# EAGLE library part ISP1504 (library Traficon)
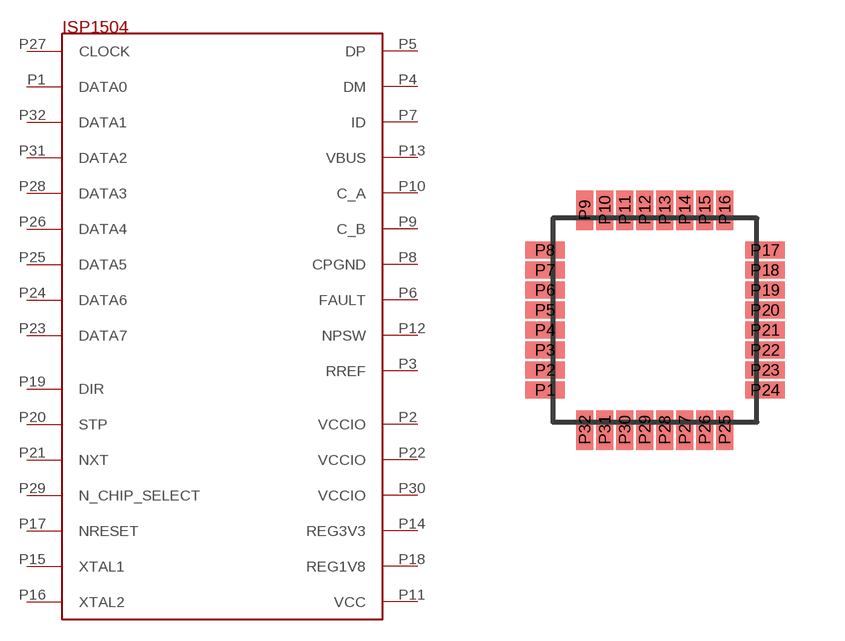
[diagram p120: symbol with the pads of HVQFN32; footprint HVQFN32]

Designator prefix U

## ISP1504  [HVQFN32]
P1  DATA0
P2  VCCIO
P3  RREF
P4  DM
P5  DP
P6  FAULT
P7  ID
P8  CPGND
P9  C_B
P10  C_A
P11  VCC
P12  NPSW
P13  VBUS
P14  REG3V3
P15  XTAL1
P16  XTAL2
P17  NRESET
P18  REG1V8
P19  DIR
P20  STP
P21  NXT
P22  VCCIO
P23  DATA7
P24  DATA6
P25  DATA5
P26  DATA4
P27  CLOCK
P28  DATA3
P29  N_CHIP_SELECT
P30  VCCIO
P31  DATA2
P32  DATA1

## Footprint HVQFN32 (pad centres in mm)
smd 0.99 x 0.42: P1 -2.75,-1.75; P2 -2.75,-1.25; P3 -2.75,-0.75; P4 -2.75,-0.25; P5 -2.75,0.25; P6 -2.75,0.75; P7 -2.75,1.25; P8 -2.75,1.75; P17 2.75,1.75; P18 2.75,1.25; P19 2.75,0.75; P20 2.75,0.25; P21 2.75,-0.25; P22 2.75,-0.75; P23 2.75,-1.25; P24 2.75,-1.75
smd 0.42 x 0.99: P9 -1.75,2.75; P10 -1.25,2.75; P11 -0.75,2.75; P12 -0.25,2.75; P13 0.25,2.75; P14 0.75,2.75; P15 1.25,2.75; P16 1.75,2.75; P25 1.75,-2.75; P26 1.25,-2.75; P27 0.75,-2.75; P28 0.25,-2.75; P29 -0.25,-2.75; P30 -0.75,-2.75; P31 -1.25,-2.75; P32 -1.75,-2.75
